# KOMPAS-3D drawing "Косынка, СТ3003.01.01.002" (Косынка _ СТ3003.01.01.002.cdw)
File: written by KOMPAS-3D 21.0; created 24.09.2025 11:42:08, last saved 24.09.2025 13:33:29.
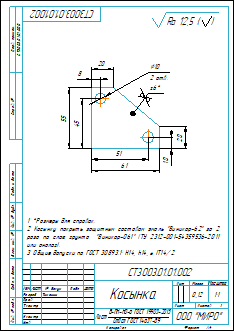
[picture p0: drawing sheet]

Sheet 1: A4, portrait

Document properties: Знак неуказанной шероховатости: 4; Параметр неуказанной шероховатости: Ra 12,5; Масса: 0.116828

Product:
- Part/product: Косынка  | designation СТ3003.01.01.002
    Материал: Лист$dБ-ПН-НО-6 ГОСТ 19903-2015;Ст3сп ГОСТ 14637-89$ (density 7850 kg/m3)
    Масса: 0.116828
    Форматы листов документа: A4

Title block, sheet 1: Наименование: Косынка; designation: СТ3003.01.01.002; Материал: Лист Б-ПН-НО-6 ГОСТ 19903-2015 Ст3сп ГОСТ 14637-89; Масса: 0,12; Количество листов документа: 1; organisation: ООО "МИРО"; Форматы листов документа: A4; stored path: C:\Users\1\Yandex.Disk\Документы\Новая папка\Стапель №2\Стапель _ СТ3003.00.00.000\Опора _ СТ3003.01.00.000\2D\Кронштейн _ СТ3003.01.01.000\Косынка _ СТ3003.01.01.002.cdw; Разработал: Тимонин

Views: Вид 1, Слева
Referenced files in C:\Users\1\Yandex.Disk\Документы\Новая папка\Стапель №2\Стапель _ СТ3003.00.00.000\Опора _ СТ3003.01.00.000\3D\Кронштейн _ СТ3003.01.01.000\: Косынка _ СТ3003.01.01.002.m3d
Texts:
  Ra 12,5
  Ra 12,5 ( )
  СТ3003.01.01.000
  СТ3003.01.01.002 Косынка
Dimensions and other numbers on the sheet: 45; 55; 51; 10; 20; 8; 61; 2 отв.; 1:1; 1; 0,12

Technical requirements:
  *Размеры для справок.
  Косынку покрыть защитным составом эмаль "Виникор-62" за 2
  раза по слою грунта  "Виникор-061" (ТУ 2312-001-54359536-2011
  или аналог).
  Общие допуски по ГОСТ 30893.1: Н14, h14, ± IT14/2.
